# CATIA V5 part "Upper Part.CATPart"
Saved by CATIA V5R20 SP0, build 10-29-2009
Part number: upp
Bounding box of the stored display mesh (mm): x 0 to 700, y -20 to 320, z 0 to 310
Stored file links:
  C:\Users\HP\Downloads\Catia Project\Catia Project\Upper Part.CATPart
  C:\Program Files (x86)\Dassault Systemes\B20\intel_a\startup\materials\Catalog.CATMaterial
  C:\Program Files (x86)\Dassault Systemes\B20\intel_a\startup\materials\red_leather.jpg
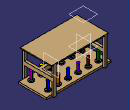
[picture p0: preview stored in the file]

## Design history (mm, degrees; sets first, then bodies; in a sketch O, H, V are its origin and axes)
Body1 (main body)
  Sketch1 on xy-plane, origin (0, 0, 0), H (1, 0, 0), V (0, 1, 0)
    line L1 (0, 0) -> (700, 0)
    line L2 (700, 0) -> (700, 300)
    line L3 (700, 300) -> (0, 300)
    line L4 (0, 300) -> (0, 0)
    length L1 = 700
    length L2 = 300
    horizontal: L1 H, L3 H
    vertical: L2 V, L4 V
  Pad1: profile Sketch1, direction (0, 0, 1), length 20
  Sketch2 on face of Pad1 from Sketch1.L3, origin (0, 300, 0), H (-1, 0, 0), V (0, 0, 1)
    line L1 (-638.5427, 300) -> (-613.0647, 300)
    line L2 (-613.0647, 300) -> (-613.0647, 0)
    line L3 (-613.0647, 0) -> (-638.5427, 0)
    line L4 (-638.5427, 0) -> (-638.5427, 300)
    point P3 (-613.0647, 0)
    length L2 = 300
    horizontal: L1 H, L3 H
    vertical: L2 V, L4 V
    coincidence: P3 H
  Pad2: profile Sketch2, direction (0, 1, 0), length 20
  Plane1: type Offset, RefPlane yz-plane, Offset 350
  Mirror1: of Pad2, about Plane1
  Plane2: type Offset, RefPlane zx-plane, Offset 150
  Mirror2: of Pad2, about Plane2
  Mirror3: of the body so far, about Plane1
  Plane3: type Offset, RefPlane xy-plane, Offset 300
  Sketch3 on face of Mirror3, origin (0, 0, 20), H (1, 0, 0), V (0, 1, 0)
    circle A1 centre (80, 240.4022) radius 25
    point P1 (80, 240.4022)
    reference projected point E1 (86.9353, 300) from vertex [face of Mirror3 | face of Mirror3 | face of Mirror3]
    reference projected line E2 (0, 300) -> (0, 0) from edge [face of Mirror3 | face of Mirror3]
    radius A1 = 25
    distance P1 E1 = 60
    distance P1 E2 = 80
  Pad3: profile Sketch3, direction (0, 0, 1), length 10
  Sketch4 on end face of Pad3, origin (0, 0, 30), H (1, 0, 0), V (0, 1, 0)
    circle A1 centre (80, 240.4022) radius 20
    reference projected circle E1 centre (80, 240.4022) radius 25 from edge [face of Pad3 from Sketch3.A1 | end face of Pad3]
    radius A1 = 20
    concentricity: E1 A1
  Pad4: profile Sketch4, direction (0, 0, 1), length 8
  Fillet1: radius 5, on face of Pad4 from Sketch4.A1
  Sketch5 on end face of Pad4, origin (0, 0, 38), H (1, 0, 0), V (0, 1, 0)
    circle A1 centre (80, 240.4022) radius 14
    reference projected circle E1 centre (80, 240.4022) radius 15 from edge [face of Fillet1 | end face of Pad4]
    radius A1 = 14
    concentricity: E1 A1
  Pad5: profile Sketch5, direction (0, 0, 1), length 80
  RectPattern1: of Pad3, Pad4, Fillet1, Pad5, direction 1 instances 6, spacing 109, along xy-plane
  Mirror4: of Pad3, Pad4, Fillet1, Pad5, about Plane2
  Mirror5: of the body so far, about Plane2
  Sketch6 on face of Mirror5, origin (0, 300, 0), H (1, 0, 0), V (0, 0, 1)
    line L1 (61.4573, 179.6487) -> (86.9353, 179.6487)
    line L2 (86.9353, 179.6487) -> (86.9353, 139.3152)
    line L3 (86.9353, 139.3152) -> (61.4573, 139.3152)
    line L4 (61.4573, 139.3152) -> (61.4573, 179.6487)
    reference projected line E1 (61.4573, 300) -> (61.4573, 0) from edge [face of Mirror5 | face of Mirror5]
    reference projected line E2 (86.9353, 0) -> (86.9353, 300) from edge [face of Mirror5 | face of Mirror5]
    horizontal: L1 H, L3 H
    vertical: L2 V, L4 V
    coincidence: L4 E1, L2 E2
  Pad6: profile Sketch6, direction (0, -1, 0), up to the existing solid (limit type 2)
  Mirror6: of the body so far, about Plane1
  Sketch7 on Plane3, origin (0, 0, 300), H (1, 0, 0), V (0, 1, 0)
    line L1 (48.1158, 320) -> (662.0906, 320)
    line L2 (662.0906, 320) -> (662.0906, -20)
    line L3 (662.0906, -20) -> (48.1158, -20)
    line L4 (48.1158, -20) -> (48.1158, 320)
    reference projected line E1 (86.9353, 320) -> (61.4573, 320) from edge [face of Mirror6 | face of Mirror6]
    reference projected line E2 (61.4573, -20) -> (86.9353, -20) from edge [face of Mirror6 | face of Mirror6]
    horizontal: L1 H, L3 H
    vertical: L2 V, L4 V
    coincidence: E1 L1, L3 E2
  Pad7: profile Sketch7, direction (0, 0, 1), length 10
  Sketch8 on face of Mirror5, origin (86.9353, 0, 0), H (0, 1, 0), V (0, 0, 1)
    line L1 (135, 179.6487) -> (165, 179.6487)
    line L2 (165, 179.6487) -> (165, 139.3152)
    line L3 (165, 139.3152) -> (135, 139.3152)
    line L4 (135, 139.3152) -> (135, 179.6487)
    reference projected line E1 (300, 179.6487) -> (0, 179.6487) from edge [face of Mirror6 | face of Mirror6]
    reference projected line E2 (300, 139.3152) -> (0, 139.3152) from edge [face of Mirror6 | face of Mirror6]
    reference intersected line E3 through (150, 0) direction (0, 1) from Plane2
    length L3 = 30
    horizontal: L1 H, L3 H
    vertical: L2 V, L4 V
    coincidence: E1 L1, E2 L3
    symmetry: L4 L2 E3
  Pad8: profile Sketch8, direction (1, 0, 0), up to the existing solid (limit type 2)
